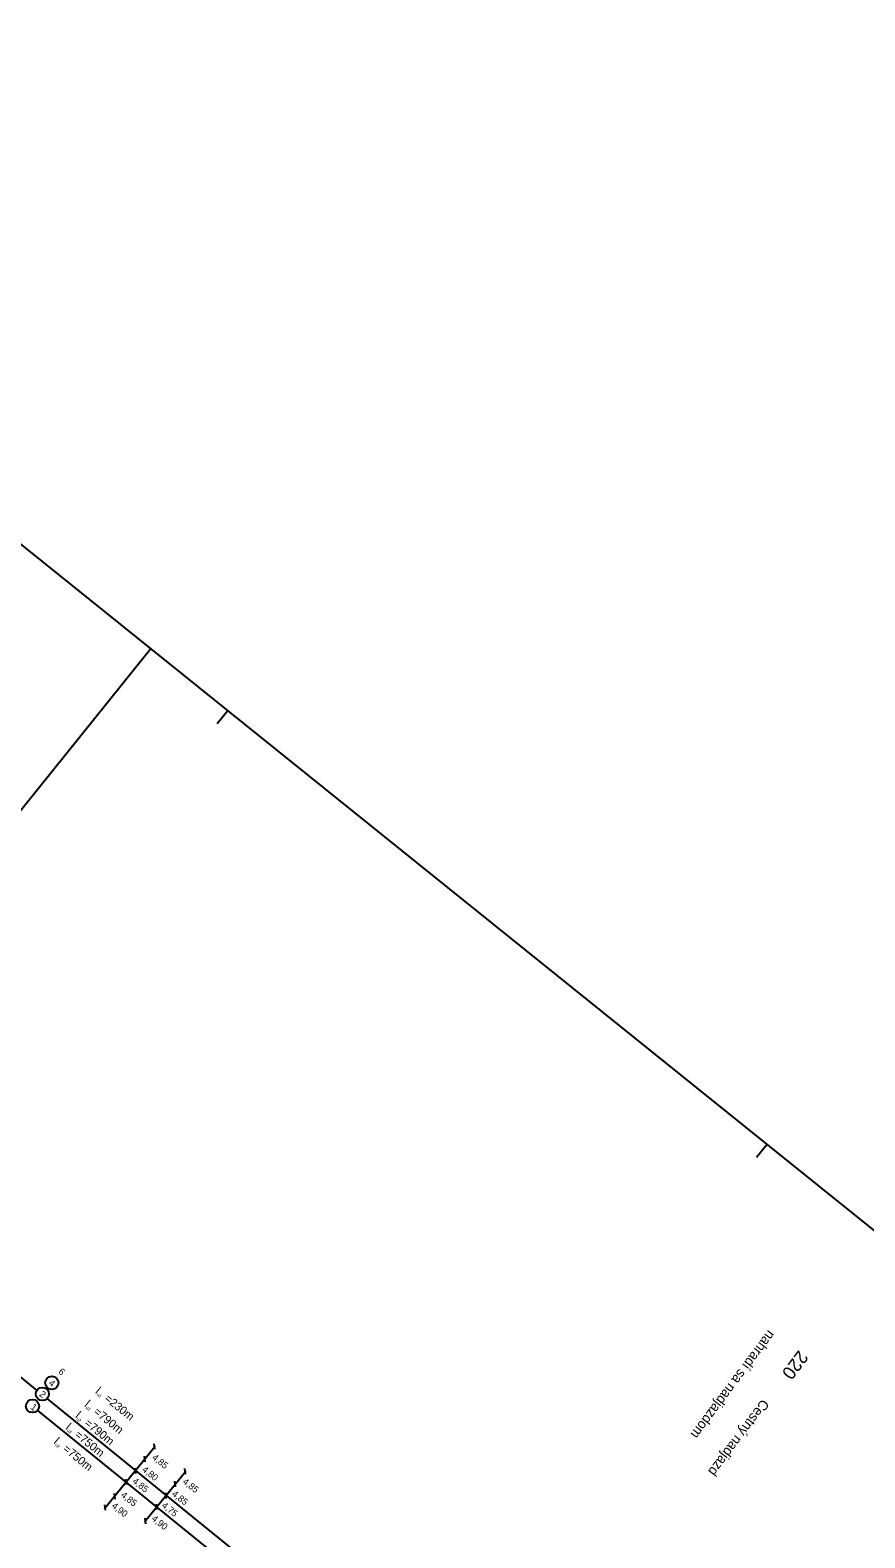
# Model space of a CAD drawing. Extents: x -491586 to -489736, y -1309039 to -1307479.
# Drawn here: x -490641.4 to -490388.1, y -1308388 to -1307930.4 of the extents above; entities that cross this region are included whole.
import ezdxf

# ---------------------------------------------------------------- set-up
doc = ezdxf.new("R2010")
doc.units = 0
for name, color, linetype in [('Level 1', 7, 'Continuous'), ('Level 10', 7, 'Continuous'), ('Level 11', 7, 'Continuous'), ('Level 6', 7, 'Continuous'), ('Level 61', 7, 'Continuous')]:
    doc.layers.add(name, color=color, linetype=linetype)

msp = doc.modelspace()

# ---------------------------------------------------------------- linework, layer by layer
at = {"layer": 'Level 1'}
for p, q in [((-490843.1, -1308177.89), (-490639.37, -1308343.26)), ((-490636.28, -1308345.77), (-490440.43, -1308504.75)), ((-490639.18, -1308349.35), (-490496.37, -1308465.13))]:
    msp.add_line(p, q, dxfattribs=at)
at = {"layer": 'Level 10'}
for p, q in [((-490603.44, -1308360.32), (-490618.85, -1308379.26)), ((-490603.54, -1308361.12), (-490603.73, -1308359.45)), ((-490606.54, -1308364.9), (-490606.73, -1308363.23)), ((-490612.15, -1308371.84), (-490612.34, -1308370.17)), ((-490609.36, -1308368.53), (-490609.54, -1308366.86)), ((-490594.17, -1308367.85), (-490606.7, -1308383.25)), ((-490594.3, -1308368.69), (-490594.48, -1308367.02)), ((-490615.64, -1308376.26), (-490615.82, -1308374.59)), ((-490600.08, -1308376.06), (-490600.27, -1308374.39)), ((-490597.33, -1308372.51), (-490597.51, -1308370.84)), ((-490618.49, -1308379.64), (-490618.68, -1308377.98)), ((-490602.87, -1308379.45), (-490603.05, -1308377.78)), ((-490606.31, -1308383.73), (-490606.5, -1308382.06))]:
    msp.add_line(p, q, dxfattribs=at)
at = {"layer": 'Level 11'}
for centre in [(-490637.69, -1308344.35), (-490634.81, -1308340.98), (-490640.67, -1308348.01)]:
    msp.add_circle(centre, 2, dxfattribs=at)
at = {"layer": 'Level 61'}
for p, q in [((-490908.8, -1307873.79), (-489763.26, -1308795.01)), ((-490791.01, -1308349.64), (-490604.88, -1308118.19)), ((-490584.64, -1308140.9), (-490581.5, -1308137)), ((-490420.99, -1308272.5), (-490417.86, -1308268.6))]:
    msp.add_line(p, q, dxfattribs=at)

# ---------------------------------------------------------------- texts
at = {"layer": 'Level 10'}
for s, height, rotation, p in [('l   =230m', 2.5, 320.9944, (-490621.8, -1308343.93)), ('l   =790m', 2.5, 320.9944, (-490625.1, -1308347.94)), ('už', 1, 320.9944, (-490621.34, -1308344.66)), ('l   =790m', 2.5, 320.9944, (-490627.9, -1308351.37)), ('už', 1, 320.9944, (-490627.48, -1308352.07)), ('už', 1, 320.9944, (-490624.68, -1308348.64)), ('l   =750m', 2.5, 320.9944, (-490630.86, -1308354.92)), ('už', 1, 320.9944, (-490630.4, -1308355.65)), ('l   =750m', 2.5, 320.9944, (-490634.42, -1308359.2)), ('už', 1, 320.9944, (-490633.96, -1308359.94)), ('4,85', 2, 321.2972, (-490604.57, -1308363.96)), ('4,85', 2, 321.2972, (-490610.54, -1308371.16)), ('4,80', 2, 321.2972, (-490607.62, -1308367.64)), ('4,85', 2, 321.2972, (-490595.32, -1308371.3)), ('4,85', 2, 321.2972, (-490614.03, -1308375.38)), ('4,85', 2, 321.2972, (-490598.55, -1308375.03)), ('4,90', 2, 321.2972, (-490616.84, -1308378.63)), ('4,75', 2, 321.2972, (-490601.66, -1308378.52)), ('4,90', 2, 321.2972, (-490604.72, -1308382.52))]:
    msp.add_text(s, height=height, rotation=rotation, dxfattribs=at).set_placement(p)
at = {"layer": 'Level 11'}
for s, p in [('6', (-490633.02, -1308337.89)), ('4', (-490635.94, -1308341.35)), ('1', (-490641.46, -1308348.66)), ('2', (-490638.79, -1308344.75))]:
    msp.add_text(s, height=2, rotation=320.9944, dxfattribs=at).set_placement(p)
at = {"layer": 'Level 6'}
for s, height, p in [('nahradí sa nadjazdom', 3, (-490417.39, -1308324.75)), ('220', 4, (-490408.16, -1308330.84)), ('Cestný nadjazd', 3, (-490419.29, -1308345.72))]:
    msp.add_text(s, height=height, rotation=233.1944, dxfattribs=at).set_placement(p)

doc.saveas('drawing.dxf')
